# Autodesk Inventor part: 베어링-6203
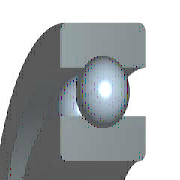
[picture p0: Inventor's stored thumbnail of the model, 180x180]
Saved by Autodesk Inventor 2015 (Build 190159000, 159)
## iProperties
IsCustomPart: 0
Created: 2016-05
Part Number: 베어링-6203
Material: 강철, 연강
Description: 깊은 그루브 볼 베어링
Document SubType Name: Modeling
Standard: KS B 2023
Designer: mduedu
Standards Organization: KS
Language: ko-KR
Size Designation: 6203 - 17 x 40 x 12
Categories: <MemberInstance><Categories><Category DisplayName="샤프트 부품" InternalName="7f7aeb1f-a693-4053-b835-cee3144e0d98" Mnemonic="SHFT"><Category DisplayName="베어링" Inter
Density: 1 g/cm^3
Appearance: 노란색
Author: mduedu
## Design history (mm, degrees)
sketch "스케치" dims "d0" = 5.98 (= -0.26 x WD + 0.26 x BD)
  geometry: L1 (3.01, 14.25)-(8.99, 14.25); L2 (6, 14.25)-(6, 11.26); L3 (6, 14.25)-(6, 17.24); L4 (3.778, 12.249)-(0, 12.249); L5 (0, 8.5)-(12, 8.5); L6 (3.778, 16.251)-(0, 16.251); L7 (0, 20)-(12, 20); L8 (12, 8.5)-(12, 12.249); L9 (8.222, 12.249)-(12, 12.249); L10 (8.222, 16.251)-(12, 16.251); L11 (12, 20)-(12, 16.251); L12 (-1.4, 0)-(8.4, 0) reference; L13 (0, -0.3)-(0, 5.3) reference
  constraints: 22 end point, 4 point on line, 2 collinear, 2 perpendicular, 2 symmetric about line, 1 midpoint, 1 parallel, 14 other
  dimensions: "d9" = 17 diameter of L5 L12 (= WD); "d11" = 40 diameter of L7 L12 (= BD); "d12" = 12 distance between parallel lines of L8 L13 (= KB); "d13" = 24.498 diameter of L9 L12 (= 0.326 x BD + 0.674 x WD)
revolve "본체" stored, may be unused: angle "d6" = 90 deg
revolve "볼" stored, may be unused: angle "d7" = 90 deg
pattern_circular "IDS_ARRAYBALL[SIMPL:T]" dims angle "d3" = 360 deg
body "Solid1"
fillet "모깎기1" dims "d1" = 0.6 (= KRS)
other parameters: "WD" = 17 [user parameter; used in 5 equation terms], "BD" = 40 [user parameter; used in 5 equation terms], "KB" = 12 [user parameter; used in 1 equation term], "KRS" = 0.6 [user parameter; used in 1 equation term], "d4" = 0, "d5" = 0, "d8" = 0, "d14" = 0, "d15" = 0, "BBA" = 0 [user parameter], "BC0" = 4750000 [user parameter], "BC" = 9560000 [user parameter], "WR" = 8.5 (= 0.5 x WD) [user parameter]
